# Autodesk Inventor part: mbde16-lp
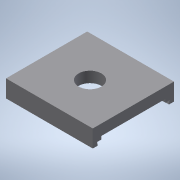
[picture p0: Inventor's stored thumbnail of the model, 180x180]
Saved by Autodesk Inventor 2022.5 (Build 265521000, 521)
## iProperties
Created: 2016-12
Part Number: mbde16-lp
Material: 一般
Document SubType Name: Modeling
Designer: imaocorp
Density: 1 g/cm^3
Appearance: 既定
Author: imaocorp
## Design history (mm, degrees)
node "mbde16-lp.x_t1"
node "60185"
node "Base1"
